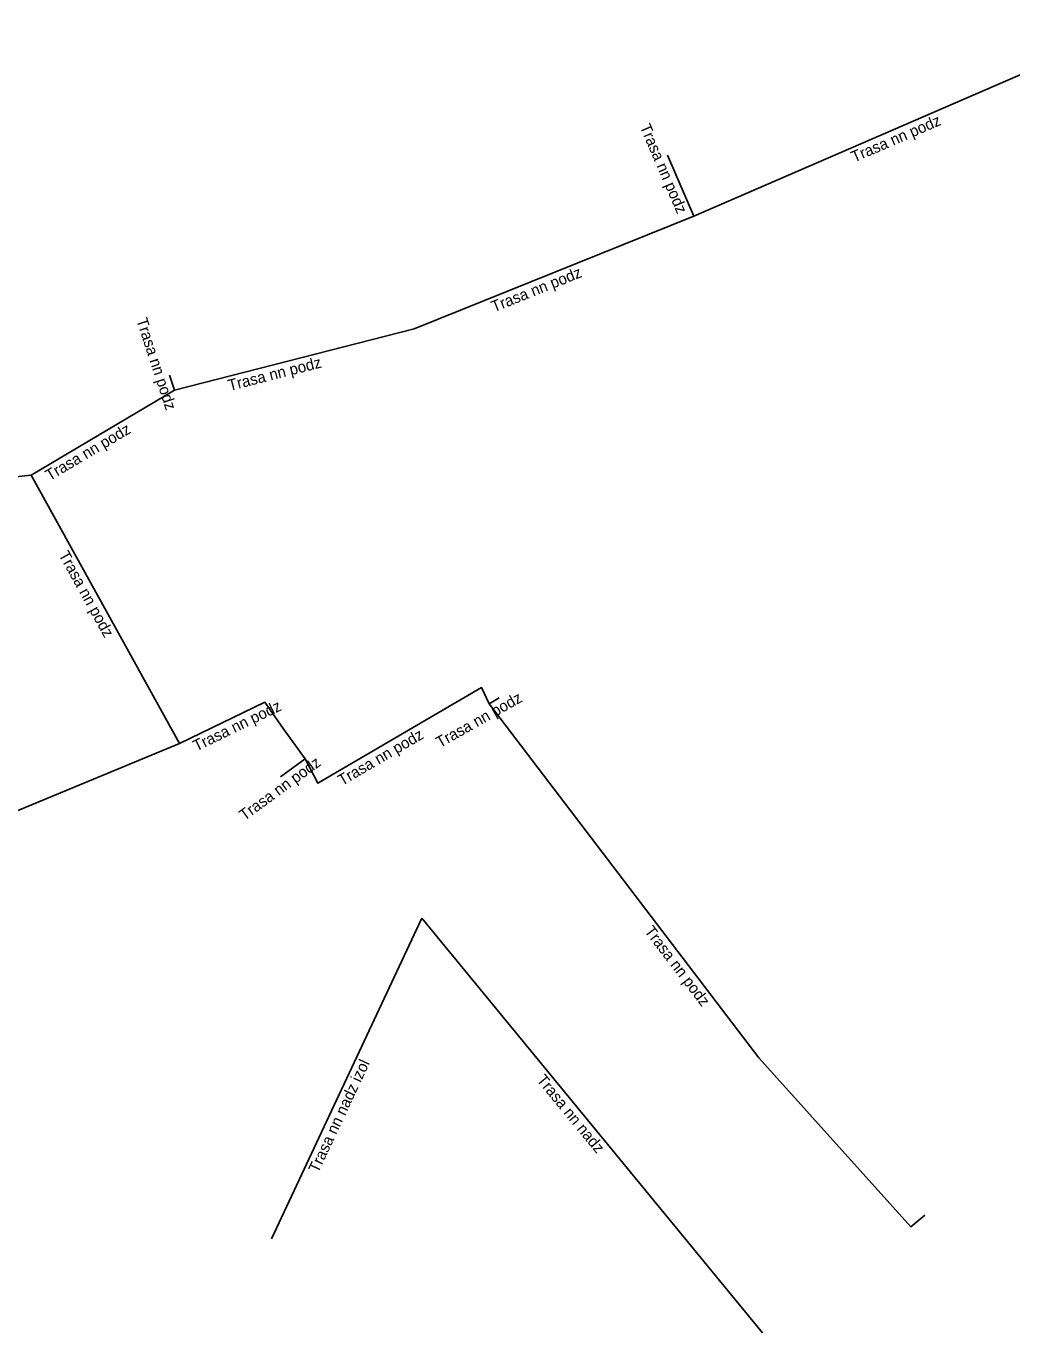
# Model space of a CAD drawing. Extents: x -711262 to -710488, y -1025222 to -1024810.
# Drawn here: x -710831.5 to -710787.6, y -1024990.3 to -1024932 of the extents above; entities that cross this region are included whole.
import ezdxf

# ---------------------------------------------------------------- set-up
doc = ezdxf.new("R2010")
doc.units = 0
doc.layers.add('Popiskový text - Ostatní atributy Trasy', color=7, linetype='Continuous')
doc.layers.add('Spojnice NN', color=7, linetype='Continuous')

msp = doc.modelspace()

# ---------------------------------------------------------------- linework, layer by layer
at = {"layer": 'Spojnice NN'}
for points in [[(-710782.2, -1024932.02), (-710801.76, -1024940.5)], [(-710801.76, -1024940.5), (-710802.93, -1024937.78)], [(-710801.76, -1024940.5), (-710814.24, -1024945.52)], [(-710824.93, -1024948.25), (-710814.24, -1024945.52)], [(-710824.93, -1024948.25), (-710825.15, -1024947.58)], [(-710831.33, -1024952.05), (-710824.93, -1024948.25)], [(-710834.52, -1024952.39), (-710831.33, -1024952.05)], [(-710831.33, -1024952.05), (-710824.71, -1024964.02)], [(-710819.1, -1024964.7), (-710818.53, -1024965.79), (-710811.23, -1024961.52), (-710810.9, -1024962.24)], [(-710824.71, -1024964.02), (-710820.9, -1024962.17), (-710820.09, -1024963.34), (-710819.1, -1024964.7)], [(-710810.9, -1024962.24), (-710810.44, -1024961.98)], [(-710810.9, -1024962.24), (-710798.87, -1024978.03), (-710792.08, -1024985.57), (-710791.45, -1024985.05)], [(-710824.71, -1024964.02), (-710832.03, -1024967.05), (-710840.28, -1024970.95), (-710854.68, -1024977.66), (-710855.49, -1024978.35)], [(-710819.1, -1024964.7), (-710820.2, -1024965.5)], [(-710813.9, -1024971.8), (-710820.6, -1024986.1)], [(-710813.9, -1024971.8), (-710798.7, -1024990.3)]]:
    msp.add_lwpolyline(points, dxfattribs=at)

# ---------------------------------------------------------------- texts
at = {"layer": 'Popiskový text - Ostatní atributy Trasy'}
for s, rotation, p in [('Trasa nn podz', 293.27482, (-710804.185, -1024936.505)), ('Trasa nn podz', 23.43856, (-710794.609, -1024938.108)), ('Trasa nn podz', 21.91214, (-710810.678, -1024944.788)), ('Trasa nn podz', 288.17802, (-710826.639, -1024945.127)), ('Trasa nn podz', 14.32593, (-710822.474, -1024948.294)), ('Trasa nn podz', 30.69972, (-710830.505, -1024952.316)), ('Trasa nn podz', 298.94476, (-710830.112, -1024955.596)), ('Trasa nn podz', 25.89955, (-710823.956, -1024964.377)), ('Trasa nn podz', 29.47589, (-710813.09, -1024964.224)), ('Trasa nn podz', 30.32471, (-710817.458, -1024965.916)), ('Trasa nn podz', 36.02737, (-710821.814, -1024967.477)), ('Trasa nn podz', 307.30285, (-710803.987, -1024972.386)), ('Trasa nn nadz izol', 64.89543, (-710818.524, -1024983.201)), ('Trasa nn nadz', 309.40726, (-710808.8, -1024979.031))]:
    msp.add_text(s, height=0.5, rotation=rotation, dxfattribs=at).set_placement(p)

doc.saveas('drawing.dxf')
